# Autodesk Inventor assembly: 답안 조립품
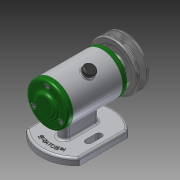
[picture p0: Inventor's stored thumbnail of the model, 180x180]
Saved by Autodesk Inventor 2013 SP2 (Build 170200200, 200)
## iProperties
Created: 2022-02
Part Number: 답안 조립품
Document SubType Name: Assembly
Designer: i
Author: i
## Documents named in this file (14)
- C:\Users\i\Desktop\720206V1010\답안 조립품.iam
- C:\Users\i\Desktop\720206V1010\본체.ipt
- C:\Users\i\Desktop\720206V1010\V벨트풀리.ipt
- C:\Users\i\Desktop\720206V1010\고무 캡.ipt
- C:\Users\i\Desktop\720206V1010\너트 M8.ipt
- C:\Users\i\Desktop\720206V1010\뒤커버.ipt
- C:\Users\i\Desktop\720206V1010\베어링 6002.ipt
- C:\Users\i\Desktop\720206V1010\볼트 M4 x 10.ipt
- C:\Users\i\Desktop\720206V1010\스프링와셔 8.ipt
- C:\Users\i\Desktop\720206V1010\앞커버.ipt
- C:\Users\i\Desktop\720206V1010\오일 실 15 x 25 x 7.ipt
- C:\Users\i\Desktop\720206V1010\축.ipt
- C:\Users\i\Desktop\720206V1010\키 3 x 3 x 12.ipt
- C:\Users\i\Desktop\720206V1010\평와셔 8 x 17.ipt
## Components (2 placed, 2 different names)
1. V벨트풀리:1
2. 고무 캡:1
